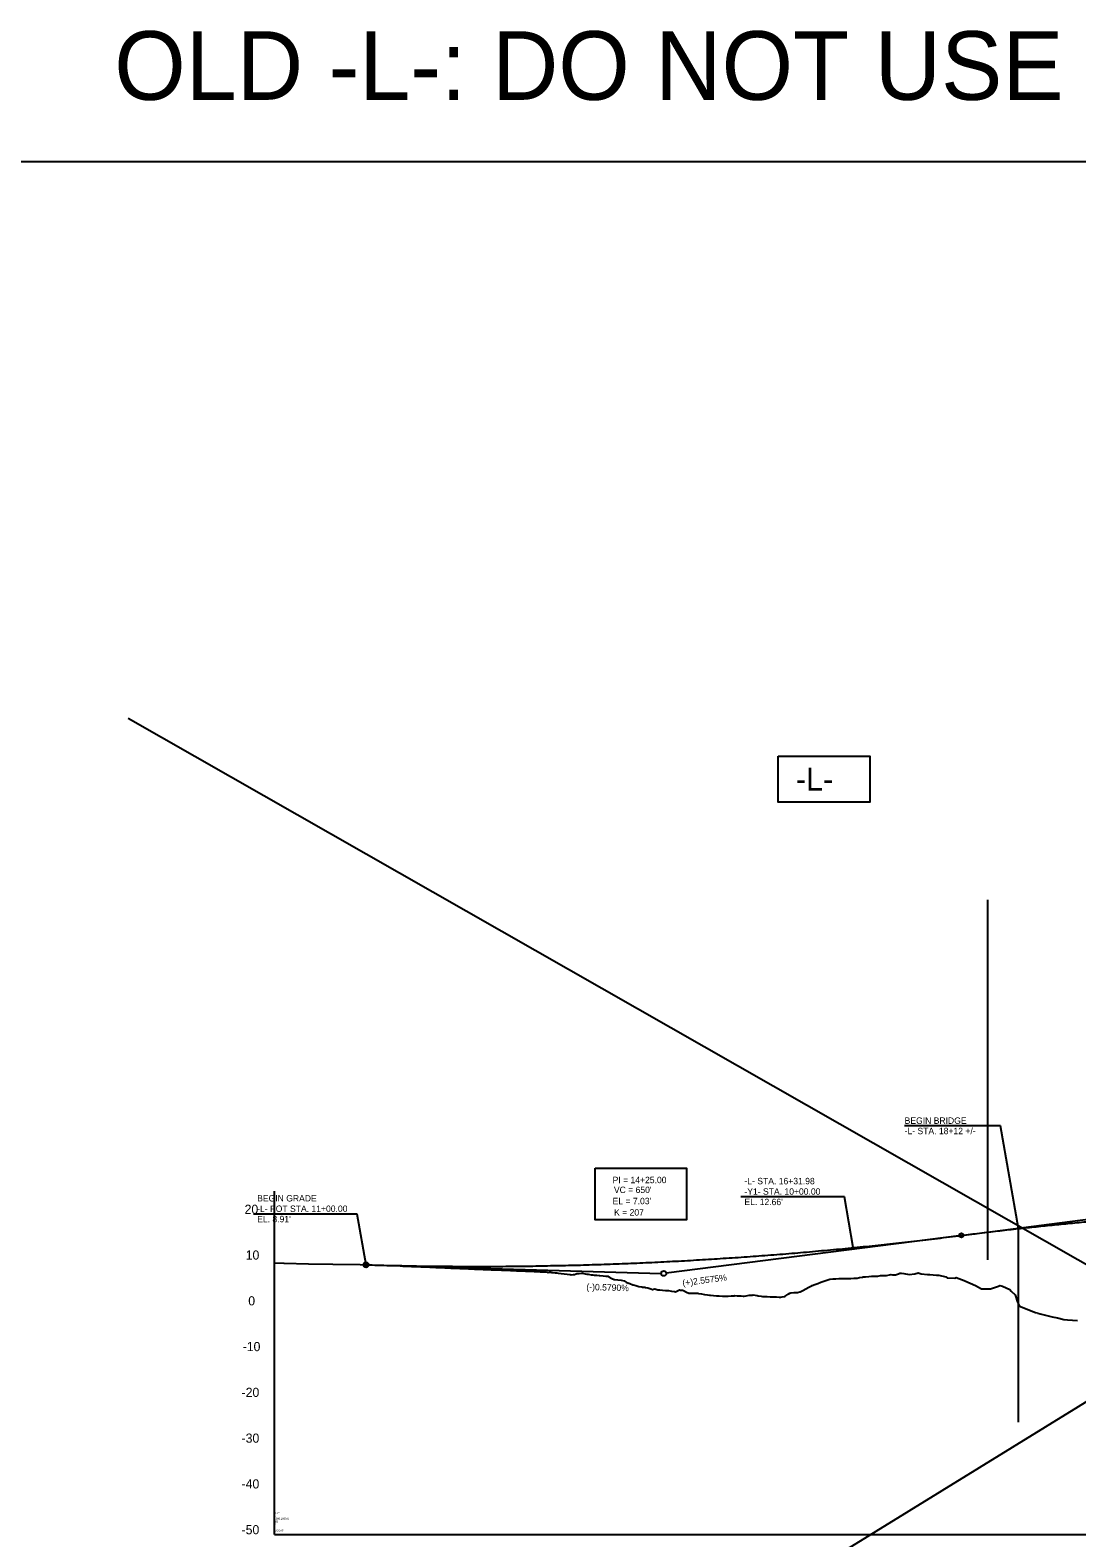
# Model space of a CAD drawing. Extents: x 1626634 to 1638383, y 876896 to 886347.
# Drawn here: x 1627535 to 1628678, y 882254 to 883901 of the extents above; entities that cross this region are included whole.
import ezdxf

# ---------------------------------------------------------------- set-up
doc = ezdxf.new("R2010")
doc.units = 0
for name, color, linetype in [('Exist Profile Cell', 7, 'Continuous'), ('Exist Vertical Profile Ground Line', 7, 'Continuous'), ('Exist Vertical Profile Vertical Axis Label', 7, 'Continuous'), ('Prop Roadway Bridge', 7, 'Continuous'), ('Prop Vertical Profile Curve Label', 7, 'Continuous'), ('Prop Vertical Profile Grade', 7, 'Continuous'), ('Prop Vertical Profile Grade Label', 7, 'Continuous'), ('Prop VPI Label', 7, 'Continuous')]:
    doc.layers.add(name, color=color, linetype=linetype)

msp = doc.modelspace()

# ---------------------------------------------------------------- linework, layer by layer
at = {"layer": 'Exist Profile Cell'}
for q in [(1627801.6, 882632.4), (1630036.7, 882257.4), (1627801.6, 882257.4)]:
    msp.add_line((1627801.6, 882257.4), q, dxfattribs=at)
at = {"layer": 'Exist Vertical Profile Ground Line'}
msp.add_lwpolyline([(1627801.6, 882554), (1627811.8, 882553.7), (1627812.3, 882553.7), (1627838.6, 882553.1), (1627865.2, 882552.7), (1627865.5, 882552.7), (1627895, 882552.1), (1627924.5, 882551.3), (1627938.7, 882550.8), (1627941.9, 882550.6), (1627945.2, 882550.5), (1627948.5, 882550.4), (1627950.8, 882550.3), (1627951.7, 882550.2), (1627955, 882550.1), (1627958.2, 882550), (1627961.5, 882549.8), (1627964.8, 882549.7), (1627968, 882549.6), (1627971.3, 882549.4), (1627974.5, 882549.3), (1627975.9, 882549.2), (1627977.8, 882549.1), (1627981, 882549), (1627984.3, 882548.9), (1627987.6, 882548.7), (1627990.8, 882548.6), (1627994.1, 882548.4), (1627997.3, 882548.3), (1628000.6, 882548.2), (1628002.7, 882548.1), (1628003.9, 882548), (1628007.1, 882547.9), (1628007.5, 882547.9), (1628010.4, 882547.8), (1628013.6, 882547.6), (1628016.9, 882547.5), (1628020.1, 882547.3), (1628023.4, 882547.2), (1628026.7, 882547.1), (1628028.6, 882547), (1628029.9, 882546.9), (1628033.2, 882546.8), (1628036.4, 882546.7), (1628038.2, 882546.6), (1628039.7, 882546.5), (1628043, 882546.4), (1628046.2, 882546.3), (1628049.5, 882546.2), (1628052.7, 882546), (1628056, 882545.9), (1628059.2, 882545.8), (1628062.5, 882545.6), (1628065.8, 882545.5), (1628069.2, 882545.3), (1628072.3, 882545.2), (1628075.5, 882545.1), (1628077.2, 882545.1), (1628078.8, 882545), (1628082.1, 882544.8), (1628085.3, 882544.7), (1628088.6, 882544.5), (1628091.8, 882544.4), (1628095.1, 882544.2), (1628098.3, 882544.1), (1628099.7, 882544), (1628100.5, 882543.7), (1628101.8, 882543.8), (1628103.1, 882543.8), (1628103.8, 882543.8), (1628104.2, 882543.7), (1628105, 882543.6), (1628108.1, 882543.2), (1628110, 882543), (1628111.4, 882542.8), (1628114.6, 882542.4), (1628117.9, 882542), (1628121.2, 882541.6), (1628124.4, 882541.2), (1628125.5, 882541), (1628127.7, 882541.2), (1628129.3, 882541.3), (1628130.9, 882542), (1628131.9, 882542.5), (1628134.2, 882542.6), (1628136.9, 882542.8), (1628137.4, 882542.7), (1628140.7, 882542.2), (1628142.8, 882541.8), (1628144, 882541.6), (1628147.2, 882541.1), (1628149.3, 882540.8), (1628150.5, 882540.7), (1628153.7, 882540.5), (1628156.2, 882540.4), (1628157, 882540.3), (1628160.3, 882540), (1628163.5, 882539.6), (1628165.6, 882539.4), (1628166.8, 882538.8), (1628170, 882537.1), (1628172.5, 882535.9), (1628173.3, 882535.8), (1628176.5, 882535.4), (1628180.1, 882535), (1628183.3, 882534.3), (1628185.7, 882532.9), (1628186.3, 882532.7), (1628189.6, 882531.4), (1628192.8, 882530.2), (1628193.3, 882530), (1628194.6, 882529.6), (1628196.1, 882529.3), (1628199.4, 882528.4), (1628202.6, 882527.7), (1628203.5, 882527.5), (1628205.9, 882527.4), (1628206.7, 882527.3), (1628209.1, 882526.6), (1628212.4, 882525.7), (1628214.3, 882525.1), (1628214.9, 882525), (1628215.6, 882525.2), (1628217, 882525.6), (1628218.9, 882525), (1628220, 882524.6), (1628221.7, 882524.7), (1628222.2, 882524.6), (1628225.4, 882524.3), (1628228.7, 882524), (1628231.9, 882523.7), (1628235.2, 882523.3), (1628238.5, 882522.7), (1628239.4, 882522.4), (1628241.7, 882523.5), (1628243.9, 882524.5), (1628245, 882524.4), (1628247.2, 882524.2), (1628248.2, 882523.7), (1628251.5, 882522.1), (1628254, 882520.8), (1628254.7, 882520.8), (1628258, 882520.8), (1628261.3, 882520.8), (1628262.6, 882520.8), (1628264.1, 882520.8), (1628264.5, 882520.7), (1628267.8, 882520.2), (1628271, 882519.6), (1628274.3, 882519.1), (1628276.4, 882518.8), (1628277.6, 882518.7), (1628280.8, 882518.4), (1628284.2, 882518.1), (1628285, 882517.9), (1628287.3, 882517.9), (1628290.6, 882517.8), (1628293.8, 882517.8), (1628294.2, 882517.8), (1628296.1, 882517.7), (1628297.1, 882517.8), (1628300.4, 882518), (1628303.6, 882518.2), (1628304.3, 882518.3), (1628306.9, 882518.2), (1628310.1, 882518.1), (1628311.2, 882518.1), (1628313.4, 882517.7), (1628314.3, 882517.6), (1628316.7, 882518), (1628319.9, 882518.6), (1628320.6, 882518.7), (1628323.2, 882518.9), (1628324.3, 882519), (1628326.4, 882518.6), (1628328.5, 882518.3), (1628329.7, 882518.1), (1628332.9, 882517.5), (1628334.3, 882517.3), (1628336.2, 882517.3), (1628339.5, 882517.3), (1628342.7, 882517), (1628344.3, 882516.8), (1628346, 882516.8), (1628349.2, 882516.8), (1628349.7, 882516.8), (1628352.5, 882516.7), (1628354.4, 882516.6), (1628355.8, 882516.8), (1628358.6, 882517.3), (1628359, 882517.6), (1628362.3, 882519.7), (1628364.4, 882521.1), (1628365.5, 882521.2), (1628368.8, 882521.5), (1628369.7, 882521.6), (1628372, 882521.6), (1628372.8, 882521.5), (1628375.3, 882522.3), (1628375.7, 882522.5), (1628378.6, 882524), (1628381.8, 882525.8), (1628385.1, 882527.5), (1628388, 882528.9), (1628388.3, 882529.2), (1628388.8, 882529.4), (1628391.6, 882530.4), (1628394.9, 882531.6), (1628398.1, 882532.8), (1628401.4, 882534), (1628404.6, 882535.2), (1628407.9, 882536.3), (1628411.1, 882536.5), (1628414.4, 882536.7), (1628417.7, 882536.9), (1628420.9, 882537), (1628424.4, 882537.1), (1628427.4, 882537), (1628431, 882536.9), (1628434, 882537.2), (1628434.4, 882537.2), (1628437.2, 882537.3), (1628437.9, 882537.3), (1628440.5, 882537.9), (1628443.7, 882538.6), (1628444.4, 882538.7), (1628447, 882538.9), (1628450.5, 882539.1), (1628453.5, 882539.4), (1628454.4, 882539.5), (1628456.8, 882539.6), (1628460.2, 882539.7), (1628463.3, 882540.2), (1628464.4, 882540.3), (1628466.5, 882540.3), (1628469.8, 882540.2), (1628473.1, 882540.9), (1628474.4, 882541.2), (1628476.3, 882541.1), (1628479.6, 882541.1), (1628482.8, 882542.2), (1628484.4, 882542.7), (1628486.1, 882542.7), (1628488.9, 882542.6), (1628494.4, 882541.3), (1628500.7, 882542.1), (1628504.4, 882543.3), (1628507.8, 882542.1), (1628514.5, 882541.2), (1628517.3, 882541.4), (1628524.5, 882540.5), (1628526.8, 882540.6), (1628534.5, 882538.7), (1628536.2, 882537.8), (1628544.5, 882537.3), (1628545.7, 882537.9), (1628554.5, 882534.9), (1628555.5, 882534.3), (1628567.1, 882529.4), (1628573.5, 882525.6), (1628577, 882525.6), (1628583.3, 882525.7), (1628592.1, 882528.6), (1628593.6, 882529.4), (1628596.3, 882528.7), (1628604.6, 882524.9), (1628606.1, 882523), (1628610.3, 882519.1), (1628612.9, 882511.1), (1628614.9, 882506.7), (1628632.6, 882500), (1628634.5, 882499.3), (1628635, 882499.2), (1628637.7, 882498.5), (1628650.6, 882495.1), (1628656.4, 882493.9), (1628663.3, 882492.2), (1628667.4, 882492), (1628678.4, 882491)], dxfattribs=at)
at = {"layer": 'Prop Roadway Bridge'}
msp.add_line((1628613.9, 882380), (1628613.9, 882591.5), dxfattribs=at)
at = {"layer": 'Prop Vertical Profile Curve Label'}
for p, q in [((1630183.7, 883324.8), (1627555.3, 881704.1)), ((1627641.7, 883149.2), (1630183.7, 881699)), ((1628580.6, 882557.4), (1628580.6, 882950.5))]:
    msp.add_line(p, q, dxfattribs=at)
msp.add_lwpolyline([(1626634.5, 883757.1), (1630394.5, 883757.1), (1630394.5, 881162.5), (1626634.5, 881162.5)], close=True, dxfattribs=at)
for centre in [(1628551.6, 882584.1), (1628551.6, 882584.1), (1627901.6, 882551.9)]:
    msp.add_circle(centre, 2.25, dxfattribs=at)
at = {"layer": 'Prop Vertical Profile Grade'}
for points in [[(1628551.6, 882584.1), (1628571.4, 882586.5), (1628591.2, 882588.9), (1628611, 882591.2), (1628630.8, 882593.3), (1628650.6, 882595.4), (1628670.4, 882597.3), (1628690.2, 882599.2), (1628710, 882600.9), (1628729.8, 882602.5), (1628749.6, 882604), (1628769.4, 882605.4), (1628789.2, 882606.7), (1628809, 882607.9), (1628828.8, 882609), (1628848.6, 882610), (1628868.4, 882610.8), (1628888.2, 882611.6), (1628908, 882612.3), (1628927.8, 882612.8), (1628947.6, 882613.3), (1628967.4, 882613.6), (1628987.2, 882613.8), (1629007, 882613.9), (1629026.8, 882613.9), (1629046.6, 882613.8), (1629066.4, 882613.6), (1629086.2, 882613.3), (1629106, 882612.9), (1629125.8, 882612.4), (1629145.6, 882611.8), (1629165.4, 882611), (1629185.2, 882610.2), (1629205, 882609.2), (1629224.8, 882608.2), (1629244.6, 882607), (1629264.4, 882605.7), (1629284.2, 882604.3), (1629304, 882602.8), (1629323.8, 882601.3), (1629343.6, 882599.5), (1629363.4, 882597.7), (1629383.2, 882595.8), (1629403, 882593.8), (1629422.8, 882591.7), (1629442.6, 882589.4), (1629462.4, 882587.1), (1629482.2, 882584.6), (1629502, 882582.1), (1629521.8, 882579.4), (1629541.6, 882576.6)], [(1627901.6, 882551.9), (1627914.6, 882551.6), (1627927.6, 882551.2), (1627940.6, 882551), (1627953.6, 882550.7), (1627966.6, 882550.5), (1627979.6, 882550.4), (1627992.6, 882550.3), (1628005.6, 882550.2), (1628018.6, 882550.2), (1628031.6, 882550.2), (1628044.6, 882550.2), (1628057.6, 882550.3), (1628070.6, 882550.5), (1628083.6, 882550.6), (1628096.6, 882550.9), (1628109.6, 882551.1), (1628122.6, 882551.4), (1628135.6, 882551.7), (1628148.6, 882552.1), (1628161.6, 882552.5), (1628174.6, 882553), (1628187.6, 882553.5), (1628200.6, 882554), (1628213.6, 882554.6), (1628226.6, 882555.2), (1628239.6, 882555.9), (1628252.6, 882556.6), (1628265.6, 882557.4), (1628278.6, 882558.1), (1628291.6, 882559), (1628304.6, 882559.8), (1628317.6, 882560.7), (1628330.6, 882561.7), (1628343.6, 882562.7), (1628356.6, 882563.7), (1628369.6, 882564.8), (1628382.6, 882565.9), (1628395.6, 882567.1), (1628408.6, 882568.2), (1628421.6, 882569.5), (1628434.6, 882570.8), (1628447.6, 882572.1), (1628460.6, 882573.4), (1628473.6, 882574.8), (1628486.6, 882576.3), (1628499.6, 882577.7), (1628512.6, 882579.3), (1628525.6, 882580.8), (1628538.6, 882582.4), (1628551.6, 882584.1)]]:
    msp.add_spline(points, degree=3, dxfattribs=at)
at = {"layer": 'Prop VPI Label'}
for p, q in [((1628594.1, 882703.7), (1628489.6, 882703.7)), ((1628613.9, 882591.5), (1628594.1, 882703.7)), ((1628551.6, 882584.1), (1629043.9, 882647)), ((1628423.9, 882626), (1628310.8, 882626)), ((1628433.6, 882570.7), (1628423.9, 882626)), ((1627891.9, 882607.2), (1627778.8, 882607.2)), ((1627901.6, 882551.9), (1627891.9, 882607.2)), ((1628551.6, 882584.1), (1628229.4, 882542.9)), ((1627901.6, 882551.9), (1628223.9, 882542.6))]:
    msp.add_line(p, q, dxfattribs=at)
for points in [[(1628351.6, 883107.4), (1628451.6, 883107.4), (1628451.6, 883057.4), (1628351.6, 883057.4)], [(1628351.6, 883107.4), (1628451.6, 883107.4), (1628451.6, 883057.4), (1628351.6, 883057.4)], [(1628351.6, 883107.4), (1628451.6, 883107.4), (1628451.6, 883057.4), (1628351.6, 883057.4)], [(1628351.6, 883107.4), (1628451.6, 883107.4), (1628451.6, 883057.4), (1628351.6, 883057.4)], [(1628151.6, 882657.4), (1628251.6, 882657.4), (1628251.6, 882601.2), (1628151.6, 882601.2)], [(1628151.6, 882657.4), (1628251.6, 882657.4), (1628251.6, 882601.2), (1628151.6, 882601.2)]]:
    msp.add_lwpolyline(points, close=True, dxfattribs=at)
for centre in [(1627901.6, 882551.9), (1628226.6, 882542.5)]:
    msp.add_circle(centre, 2.75, dxfattribs=at)

# ---------------------------------------------------------------- texts
at = {"layer": 'Exist Profile Cell'}
for s, p in [('RDY', (1627801.6, 882280.1)), ('5', (1627801.6, 882267.1)), ('1000.000000', (1627801.6, 882273.6)), ('-50', (1627801.6, 882270.4)), ('1', (1627801.6, 882263.9)), ('L', (1627801.6, 882276.9)), ('NOGAP', (1627801.6, 882260.6))]:
    msp.add_text(s, height=2, dxfattribs=at).set_placement(p)
at = {"layer": 'Exist Vertical Profile Vertical Axis Label'}
for s, p in [('20', (1627769, 882607.6)), ('10', (1627770.2, 882557.6)), ('0', (1627773, 882507.6)), ('-10', (1627766.9, 882457.6)), ('-20', (1627765.7, 882407.6)), ('-30', (1627765.7, 882357.6)), ('-40', (1627765.7, 882307.6)), ('-50', (1627765.7, 882257.6))]:
    msp.add_text(s, height=10, dxfattribs=at).set_placement(p)
at = {"layer": 'Prop Vertical Profile Curve Label'}
for s, height, p in [('OLD -L-: DO NOT USE', 75, (1627626.7, 883824.4)), ('-L-', 25, (1628370.8, 883069.9)), ("VC = 650'", 7, (1628172.2, 882630.3)), ('K = 207', 7, (1628172.4, 882605.7))]:
    msp.add_text(s, height=height, dxfattribs=at).set_placement(p)
at = {"layer": 'Prop Vertical Profile Grade Label'}
for s, rotation, p in [('(-)0.5790%', 358.3417, (1628142.1, 882524.4)), ('(+)2.5575%', 7.2872, (1628247.5, 882528.6))]:
    msp.add_text(s, height=7, rotation=rotation, dxfattribs=at).set_placement(p)
at = {"layer": 'Prop VPI Label'}
for s, p in [('BEGIN BRIDGE', (1628489.6, 882705.9)), ('-L- STA. 18+12 +/-', (1628489.6, 882694.6)), ('PI = 14+25.00', (1628170.8, 882641.1)), ('-L- STA. 16+31.98', (1628314.7, 882639.9)), ('BEGIN GRADE', (1627782.7, 882621.1)), ('-Y1- STA. 10+00.00', (1628314.7, 882628.5)), ('-L- POT STA. 11+00.00', (1627782.7, 882609.7)), ("EL = 7.03'", (1628170.8, 882618.1)), ("EL. 12.66'", (1628314.7, 882617.1)), ("EL. 8.91'", (1627782.7, 882598.4))]:
    msp.add_text(s, height=7, dxfattribs=at).set_placement(p)

doc.saveas('drawing.dxf')
